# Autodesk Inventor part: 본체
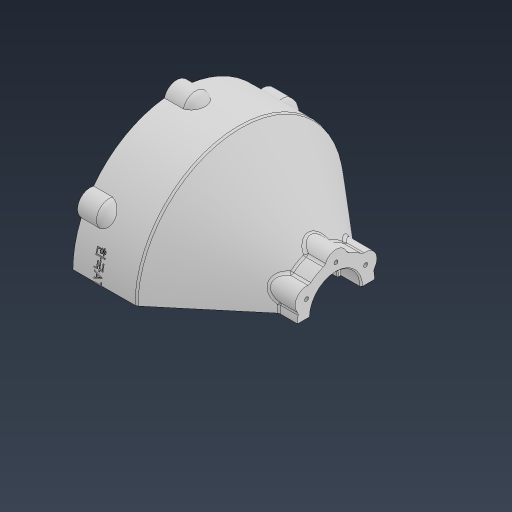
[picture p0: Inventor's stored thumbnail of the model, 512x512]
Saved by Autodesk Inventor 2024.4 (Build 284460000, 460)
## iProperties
Created: 2026-05
Part Number: 본체
Material: 일반
Document SubType Name: Modeling
Designer: user
Density: 1 g/cm^3
Appearance: 기본값
Author: user
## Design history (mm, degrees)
sketch "스케치1"
  geometry: L1 (0, 0)-(0, 82); L2 (0, 82)-(50, 82); L3 (50, 82)-(111.375, 30.5); L4 (111.375, 30.5)-(126, 30.5); L5 (126, 30.5)-(126, 0); L6 (126, 0)-(0, 0); L7 (0, 73)-(37, 73); L8 (37, 73)-(37, 68); L9 (37, 68)-(42, 68); L10 (42, 68)-(42, 56); L11 (42, 56)-(62, 56); L12 (62, 56)-(62, 40); L13 (62, 40)-(78, 40); L14 (78, 40)-(78, 37); L15 (78, 37)-(82, 37); L16 (82, 37)-(82, 20); L17 (82, 20)-(94, 20); L18 (94, 20)-(94, 17.5); L19 (94, 17.5)-(110, 17.5); L20 (110, 17.5)-(110, 20); L21 (110, 20)-(126, 20); 1 further point
  constraints: 42 end point, 17 perpendicular, 2 point on line, 2 vertical, 1 midpoint, 1 parallel
  dimensions: "d0" = 164 diameter of L2 L6; "d1" = 126 distance between parallel lines of L5 L1; "d2" = 50 distance of L1.end L2.end; "d3" = 40 deg angle of L3 L2; "d4" = 61 diameter of L4 L6; "d5" = 37 distance of L7.start L7.end; "d6" = 146 diameter of L7 L6; "d7" = 5 distance of L8.end L9.end; "d8" = 136 diameter of L9 L6; "d9" = 25 distance from line of point (62, 48) L8; "d10" = 112 diameter of L11 L6; "d11" = 16 distance of L12.end L13.end; "d12" = 4 distance of L14.end L15.end; "d13" = 80 diameter of L13 L6; "d14" = 74 diameter of L15 L6; "d15" = 40 diameter of L17 L6; "d16" = 40 diameter of L21 L6; "d17" = 35 diameter of L19 L6; "d18" = 12 distance of L16.end L17.end; "d19" = 16 distance of L20.end L21.end
revolve "회전1" sketch "스케치1" stored, may be unused: angle "d20" = 90 deg
sketch "스케치2" dims "d24" = 54
  geometry: L1 (0, 0)-(0, 94.338); L2 (0, 0)-(-67.233, 38.817); C1 r 30.5 at (0, 0) reference; A1 r 20 centre (0, 0) between (-19.224, 5.519) and (-14.391, 13.889) reference; A2 r 9 centre (-23.383, 13.5) between (-14.391, 13.889) and (-19.224, 5.519); A3 r 20 centre (0, 0) between (-14.391, 13.889) and (-19.224, 5.519); 1 further point
  constraints: 6 point on circle, 4 end point, 2 centre point, 2 coincident, 1 concentric, 1 point on line, 1 vertical, 3 other
  dimensions: "d21" = 60 deg angle of L2 L1; "d23" = 18 diameter of A2
sketch "스케치4" dims "d39" = 124
  geometry: L1 (0, 0)-(0, -112.084); L2 (0, 0)-(98.539, -56.892); C1 r 68 at (0, 0) reference; 1 further point
  constraints: 4 end point, 1 coincident, 1 point on line, 1 vertical, 1 vertical alignment, 2 other
  dimensions: "d40" = 60 deg angle of L1 L2
hole "구멍2" sketch "스케치4" at (0, -62) diameter "d41" = 3.242; stored, may be unused: countersink angle "d45" = 90 deg, drill point angle "d47" = 118 deg; dims "d42" = 8, "d43" = 4, "d44" = 2, "d46" = 10
sketch "스케치5" dims "d51" = 158
  geometry: L1 (0, 0)-(0, -139.331); L2 (0, 0)-(112.907, -65.187); C1 r 82 at (0, 0) reference; 1 further point
  constraints: 4 end point, 1 coincident, 1 point on line, 1 vertical, 1 vertical alignment, 2 other
  dimensions: "d52" = 60 deg angle of L1 L2
hole "구멍3" sketch "스케치5" at (0, -79) diameter "d53" = 4.917; stored, may be unused: countersink angle "d57" = 90 deg, drill point angle "d59" = 118 deg; dims "d54" = 12, "d55" = 4, "d56" = 2, "d58" = 14
sketch "스케치6" dims "d63" = 153.0712
  geometry: L1 (0, 0)-(-38.268, -66.282); C1 r 2.458 at (0, -79) reference; C2 r 73 at (0, 0) reference; C3 r 82 at (0, 0) reference; C4 r 1.621 at (-23.383, -13.5) reference; C5 r 10 at (0, -79); 3 further points
  constraints: 2 coincident, 2 end point, 1 centre point, 1 point on line, 3 other
  dimensions: "d65" = 20 diameter of C5
extrude "돌출2" join sketch "스케치6" distance "d66" = 15; taper "d67" = 0 deg
sketch "스케치7"
  geometry: L1 (9.702, -81.424)-(-9.702, -81.424); A1 r 10 centre (0, -79) between (-9.702, -81.424) and (9.702, -81.424) reference
  constraints: 2 end point, 1 horizontal
revolve "회전2" sketch "스케치7" stored, may be unused: angle "d68" = 90 deg
extrude "돌출3" join sketch "스케치2" stored distance "d72" = 15; taper "d73" = 0 deg
hole "구멍4" sketch "스케치2" diameter "d77" = 3.242; stored, may be unused: countersink angle "d81" = 90 deg, drill point angle "d83" = 118 deg; dims "d78" = 8, "d79" = 4, "d80" = 2, "d82" = 10
chamfer "모따기1" distance "d87" = 1; stored, may be unused: second distance "d88" = 2, angle "d89" = 45 deg
fillet "모깎기1" dims "d90" = 3
chamfer "모따기2" distance "d91" = 1; stored, may be unused: second distance "d92" = 2, angle "d93" = 45 deg
fillet "모깎기2" dims "d94" = 3
chamfer "모따기3" distance "d95" = 1; stored, may be unused: second distance "d96" = 2, angle "d97" = 45 deg
fillet "모깎기3" dims "d98" = 1
fillet "모깎기4" dims "d99" = 3
chamfer "모따기4" distance "d100" = 1; stored, may be unused: second distance "d101" = 2, angle "d102" = 45 deg
chamfer "모따기5" distance "d103" = 1; stored, may be unused: second distance "d104" = 2, angle "d105" = 45 deg
fillet "모깎기5" dims "d106" = 0.6
chamfer "모따기6" distance "d107" = 1; stored, may be unused: second distance "d108" = 2, angle "d109" = 45 deg
fillet "모깎기6" dims "d110" = 3
sketch "스케치8" dims "d0" = 164, "d1" = 126, "d2" = 50, "d3" = 40 deg, "d4" = 61, "d5" = 37, "d6" = 146, "d7" = 5, "d8" = 136, "d9" = 25, "d10" = 112, "d11" = 16, "d12" = 4, "d13" = 80, "d14" = 74, "d15" = 40, "d16" = 40, "d17" = 35, "d18" = 12, "d19" = 16
  geometry: L1 (0, 32.31)-(0, -32.31) reference; 4 further points
  constraints: 2 midpoint, 1 horizontal alignment, 1 other
  dimensions: "d111" = 20 distance of point (20, 0) point (0, 0)
feature "엠보싱1" sketch "스케치8" dims "d0" = 164, "d1" = 126, "d2" = 50, "d3" = 40 deg, "d4" = 61, "d5" = 37, "d6" = 146, "d7" = 5, "d8" = 136, "d9" = 25, "d10" = 112, "d11" = 16, "d12" = 4, "d13" = 80, "d14" = 74, "d15" = 40, "d16" = 40, "d17" = 35, "d18" = 12, "d19" = 16, "d112" = 0.5, "d113" = 0
sketch "스케치9"
  geometry: A1 r 10 centre (68.416, 118.5) between (75.366, 111.31) and (65.664, 128.114) reference; 2 further points
  constraints: 1 coincident
hole "구멍5" sketch "스케치9" at (68.416, 118.5) diameter "d114" = 4.917; stored, may be unused: countersink angle "d118" = 90 deg, drill point angle "d120" = 118 deg; dims "d115" = 12, "d116" = 4, "d117" = 2, "d119" = 14
node "솔리드1"
pattern_circular "원형 패턴2" dims angle "d49" = 360 deg
pattern_circular "원형 패턴3" dims angle "d61" = 360 deg
pattern_circular "원형 패턴4" dims angle "d70" = 360 deg
pattern_circular "원형 패턴5" dims angle "d75" = 360 deg
pattern_circular "원형 패턴6" dims angle "d85" = 360 deg
pattern_circular "원형 패턴7" dims angle "d122" = 360 deg
feature "A9D066F2-1C7D-4E18-AEED-F7BC21143FA4" dims "d53" = 4.917, "d54" = 12, "d55" = 4, "d56" = 2, "d57" = 90 deg, "d58" = 14, "d59" = 118 deg
